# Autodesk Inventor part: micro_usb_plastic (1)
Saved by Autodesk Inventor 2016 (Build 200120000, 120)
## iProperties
Created: 2016-09
Part Number: micro_usb_plastic (1)
Material: Generic
Document SubType Name: Modeling
Designer: Administrator
Appearance: Generic
Author: Administrator
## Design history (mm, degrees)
feature "Body1"
body "Solid1"
